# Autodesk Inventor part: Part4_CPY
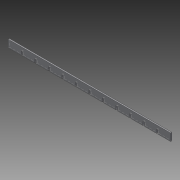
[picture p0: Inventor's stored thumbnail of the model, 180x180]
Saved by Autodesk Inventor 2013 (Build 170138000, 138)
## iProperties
Created: 2013-06
Part Number: Part4_CPY
Material: Generic
Document SubType Name: Modeling
Designer: jpfenske
Density: 1 g/cm^3
Author: jpfenske
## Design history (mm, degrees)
sketch "Sketch1"
  geometry: L1 (0, 0)-(838.2, 0); L2 (838.2, 0)-(838.2, 38.1); L3 (838.2, 38.1)-(0, 38.1); L4 (0, 38.1)-(0, 0); L5 (66.675, 0)-(66.675, 19.05); L6 (66.675, 19.05)-(73.025, 19.05); L7 (73.025, 19.05)-(73.025, 0); L8 (73.025, 0)-(66.675, 0); L9 (142.875, 0)-(136.525, 0); L10 (136.525, 0)-(136.525, 19.05); L11 (142.875, 19.05)-(142.875, 0); L12 (136.525, 19.05)-(142.875, 19.05); L13 (212.725, 0)-(206.375, 0); L14 (206.375, 0)-(206.375, 19.05); L15 (212.725, 19.05)-(212.725, 0); L16 (206.375, 19.05)-(212.725, 19.05); L17 (282.575, 0)-(276.225, 0); L18 (276.225, 0)-(276.225, 19.05); L19 (282.575, 19.05)-(282.575, 0); L20 (276.225, 19.05)-(282.575, 19.05); L21 (352.425, 0)-(346.075, 0); L22 (346.075, 0)-(346.075, 19.05); L23 (352.425, 19.05)-(352.425, 0); L24 (346.075, 19.05)-(352.425, 19.05); L25 (422.275, 0)-(415.925, 0); L26 (415.925, 0)-(415.925, 19.05); L27 (422.275, 19.05)-(422.275, 0); L28 (415.925, 19.05)-(422.275, 19.05); L29 (492.125, 0)-(485.775, 0); L30 (485.775, 0)-(485.775, 19.05); L31 (492.125, 19.05)-(492.125, 0); L32 (485.775, 19.05)-(492.125, 19.05); L33 (561.975, 0)-(555.625, 0); L34 (555.625, 0)-(555.625, 19.05); L35 (561.975, 19.05)-(561.975, 0); L36 (555.625, 19.05)-(561.975, 19.05); L37 (631.825, 0)-(625.475, 0); L38 (625.475, 0)-(625.475, 19.05); L39 (631.825, 19.05)-(631.825, 0); L40 (625.475, 19.05)-(631.825, 19.05); L41 (701.675, 0)-(695.325, 0); L42 (695.325, 0)-(695.325, 19.05); L43 (701.675, 19.05)-(701.675, 0); L44 (695.325, 19.05)-(701.675, 19.05); L45 (771.525, 0)-(765.175, 0); L46 (765.175, 0)-(765.175, 19.05); L47 (771.525, 19.05)-(771.525, 0); L48 (765.175, 19.05)-(771.525, 19.05)
  constraints: 96 end point, 4 parallel, 3 perpendicular, 2 horizontal, 1 point on line, 80 other
  dimensions: "d0" = 838.2 distance of L3.end L2.end; "d1" = 38.1 distance of L1.end L2.end; "d2" = 19.05 distance of L5.start L5.end; "d3" = 6.35 distance of L5.end L6.end; "d6" = 69.85 distance of L7.end L9.start
extrude "Extrusion1" new body sketch "Sketch1" distance "d11" = 6.35; taper "d12" = 0 deg
body "Solid1"
other parameters: "d9" = 25.4
